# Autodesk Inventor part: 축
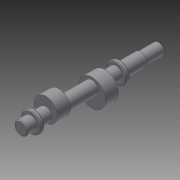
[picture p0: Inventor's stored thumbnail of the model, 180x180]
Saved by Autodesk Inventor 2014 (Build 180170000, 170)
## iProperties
Created: 2014-12
Part Number: 축
Material: 일반
Document SubType Name: Modeling
Designer: Owner
Density: 1 g/cm^3
Appearance: 기본값
Author: Owner
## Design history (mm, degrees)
sketch "스케치1"
  geometry: C1 r 8.5 at (0, 0); 1 further point
  constraints: 1 centre point, 1 coincident
  dimensions: "d0" = 17 diameter of C1
extrude "돌출1" new body sketch "스케치1" distance "d1" = 13; taper "d2" = 0 deg
sketch "스케치2"
  geometry: C1 r 8.5 at (0, 0) reference; C2 r 13 at (0, 0)
  constraints: 1 centre point, 1 coincident
  dimensions: "d3" = 26 diameter of C2
extrude "돌출2" join sketch "스케치2" distance "d4" = 5; taper "d5" = 0 deg
sketch "스케치3"
  geometry: C1 r 13 at (0, 0) reference; C2 r 8.5 at (0, 0)
  constraints: 1 centre point, 1 coincident
  dimensions: "d6" = 17 diameter of C2
extrude "돌출3" join sketch "스케치3" distance "d7" = 14.5; taper "d8" = 0 deg
sketch "스케치4"
  geometry: C1 r 8.5 at (0, 0) reference; C2 r 15 at (0, -5); 1 further point
  constraints: 1 centre point, 1 coincident, 1 vertical alignment
  dimensions: "d9" = 5 distance of C1.centre point (0, -5); "d10" = 30 diameter of C2
extrude "돌출4" join sketch "스케치4" distance "d11" = 17; taper "d12" = 0 deg
sketch "스케치5"
  geometry: C1 r 8.5 at (0, 5); 1 further point
  constraints: 1 centre point, 1 coincident
  dimensions: "d13" = 17 diameter of C1
extrude "돌출5" join sketch "스케치5" distance "d14" = 43; taper "d15" = 0 deg
sketch "스케치6"
  geometry: C1 r 8.5 at (0, 0) reference; C2 r 17.5 at (0, 6); 1 further point
  constraints: 1 centre point, 1 coincident, 1 vertical alignment
  dimensions: "d16" = 6 distance of C1.centre point (0, 6); "d17" = 35 diameter of C2
extrude "돌출6" join sketch "스케치6" distance "d18" = 17; taper "d19" = 0 deg
sketch "스케치7"
  geometry: C1 r 8.5 at (0, -6); 1 further point
  constraints: 1 centre point, 1 coincident
  dimensions: "d20" = 17 diameter of C1
extrude "돌출7" join sketch "스케치7" distance "d21" = 14.5; taper "d22" = 0 deg
sketch "스케치8"
  geometry: C1 r 8.5 at (0, 0) reference; C2 r 13 at (0, 0)
  constraints: 1 centre point, 1 coincident
  dimensions: "d23" = 26 diameter of C2
extrude "돌출8" join sketch "스케치8" distance "d24" = 5; taper "d25" = 0 deg
sketch "스케치9"
  geometry: C1 r 13 at (0, 0) reference; C2 r 8.5 at (0, 0)
  constraints: 1 centre point, 1 coincident
  dimensions: "d26" = 17 diameter of C2
extrude "돌출9" join sketch "스케치9" distance "d27" = 27; taper "d28" = 0 deg
sketch "스케치10"
  geometry: C1 r 8.5 at (0, 0) reference; C2 r 7.5 at (0, 0)
  constraints: 1 centre point, 1 coincident
  dimensions: "d29" = 15 diameter of C2
extrude "돌출10" join sketch "스케치10" distance "d30" = 24; taper "d31" = 0 deg
node "작업 평면1"
sketch "스케치11"
  geometry: L1 (7.5, 24)-(-7.5, 24) reference; L2 (7.5, 24)-(-7.5, 24) reference; L3 (-7.5, 0)-(7.5, 0) reference; L4 (7.5, 0)-(7.5, 24) reference; L5 (-7.5, 0)-(-7.5, 24) reference; L6 (-2.5, 24)-(-2.5, 6.5); L7 (2.5, 24)-(2.5, 6.5); L8 (-2.5, 24)-(2.5, 24); A1 r 2.5 centre (0, 6.5) between (-2.5, 6.5) and (2.5, 6.5); 2 further points
  constraints: 6 end point, 2 parallel, 2 point on circle, 2 point on line, 2 tangent, 1 centre point, 1 collinear, 1 midpoint, 1 vertical alignment
  dimensions: "d32" = 5 diameter of A1; "d33" = 20 dimension on A1 L1
extrude "돌출11" cut sketch "스케치11" distance "d34" = 3; taper "d35" = 0 deg
chamfer "모따기1" distance "d36" = 1; stored, may be unused: second distance "d37" = 2, angle "d38" = 45 deg
chamfer "모따기2" distance "d39" = 1; stored, may be unused: second distance "d40" = 2, angle "d41" = 45 deg
chamfer "모따기3" distance "d42" = 1; stored, may be unused: second distance "d43" = 2, angle "d44" = 45 deg
chamfer "모따기4" distance "d45" = 1; stored, may be unused: second distance "d46" = 2, angle "d47" = 45 deg
chamfer "모따기5" distance "d48" = 1; stored, may be unused: second distance "d49" = 2, angle "d50" = 45 deg
chamfer "모따기6" distance "d51" = 1; stored, may be unused: second distance "d52" = 2, angle "d53" = 45 deg
node "솔리드1"
node "투영된 루프1"
